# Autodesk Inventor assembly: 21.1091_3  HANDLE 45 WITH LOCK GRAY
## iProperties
Created: 2007-03
Part Number: 21.1091_3  HANDLE 45 WITH LOCK GRAY
Document SubType Name: Assembly
Designer: Andy Moles
Translation Standard: STEP AP214IS
File Name: 1000-U626_ASM
Preprocessor: PRO/ENGINEER BY PARAMETRIC TECHNOLOGY CORPORATION, 2003200
Postprocessor: Build: 344b, Release: 11 SP2 - Date: Fri 08/18/2006
Sent Units: MILLIMETERS
Uncertainty: 0.018480335636049998
Author: Andy Moles
